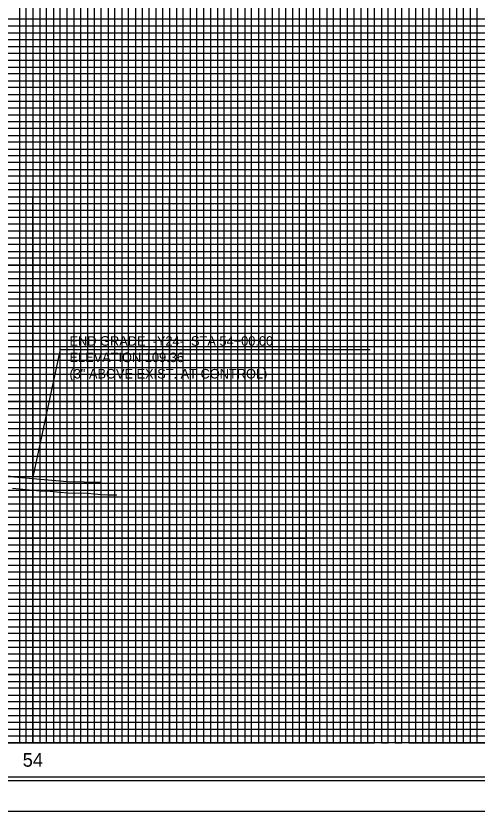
# Model space of a CAD drawing. Extents: x 2345490 to 2436403, y 465165 to 573888.
# Drawn here: x 2386154 to 2386492, y 515088 to 515670 of the extents above; entities that cross this region are included whole.
import ezdxf

# ---------------------------------------------------------------- set-up
doc = ezdxf.new("R2010")
doc.units = 0
for name, color, linetype in [('Old_Level_1', 7, 'Continuous'), ('Old_Level_18', 7, 'Continuous'), ('Old_Level_2', 7, 'Continuous'), ('Old_Level_41', 7, 'Continuous'), ('Old_Level_42', 7, 'Continuous'), ('Old_Level_43', 7, 'Continuous'), ('Old_Level_50', 7, 'Continuous'), ('Old_Level_51', 7, 'Continuous'), ('Old_Level_57', 7, 'Continuous'), ('Old_Level_61', 7, 'Continuous'), ('Old_Level_62', 7, 'Continuous'), ('Old_Level_63', 7, 'Continuous')]:
    doc.layers.add(name, color=color, linetype=linetype)

msp = doc.modelspace()

# ---------------------------------------------------------------- linework, layer by layer
at = {"layer": 'Old_Level_1'}
msp.add_lwpolyline([(2386151.799, 515323.96225), (2386156.799, 515323.5325), (2386161.799, 515323.10275), (2386166.799, 515322.673), (2386171.799, 515322.243), (2386176.799, 515322.05025), (2386181.799, 515321.5945), (2386186.799, 515321.139), (2386191.799, 515320.6835), (2386196.799, 515320.522), (2386201.799, 515320.5785), (2386206.799, 515320.42725), (2386211.799, 515319.972), (2386216.799, 515319.5165), (2386221.799, 515319.18175), (2386226.799, 515319.24875), (2386228.049, 515319.2575)], dxfattribs=at)
at = {"layer": 'Old_Level_18'}
msp.add_lwpolyline([(2387416.79875, 516162.5265), (2385916.79875, 516162.5265), (2385916.79875, 515112.5265), (2387416.79875, 515112.5265)], close=True, dxfattribs=at)
at = {"layer": 'Old_Level_2'}
for p, q in [((2386166.799, 515331.1265), (2386187.00475, 515425.63)), ((2386187.00475, 515425.63), (2386413.6105, 515425.63)), ((2386001.799, 515347.9565), (2386166.799, 515331.1265))]:
    msp.add_line(p, q, dxfattribs=at)
at = {"layer": 'Old_Level_41'}
msp.add_line((2387416.79875, 515137.5265), (2385916.79875, 515137.5265), dxfattribs=at)
for points in [[(2385916.79875, 516162.5265), (2385966.79875, 516162.5265), (2385966.79875, 515137.5265), (2386016.79875, 515137.5265), (2386016.79875, 516162.5265), (2386066.79875, 516162.5265), (2386066.79875, 515137.5265), (2386116.79875, 515137.5265), (2386116.79875, 516162.5265), (2386166.79875, 516162.5265), (2386166.79875, 515137.5265), (2386216.79875, 515137.5265), (2386216.79875, 516162.5265), (2386266.79875, 516162.5265), (2386266.79875, 515137.5265), (2386316.79875, 515137.5265), (2386316.79875, 516162.5265), (2386366.79875, 516162.5265), (2386366.79875, 515137.5265), (2386416.79875, 515137.5265), (2386416.79875, 516162.5265), (2386466.79875, 516162.5265), (2386466.79875, 515137.5265), (2386516.79875, 515137.5265)], [(2385991.79875, 515137.5265), (2385991.79875, 516162.5265), (2386041.79875, 516162.5265), (2386041.79875, 515137.5265), (2386091.79875, 515137.5265), (2386091.79875, 516162.5265), (2386141.79875, 516162.5265), (2386141.79875, 515137.5265), (2386191.79875, 515137.5265), (2386191.79875, 516162.5265), (2386241.79875, 516162.5265), (2386241.79875, 515137.5265), (2386291.79875, 515137.5265), (2386291.79875, 516162.5265), (2386341.79875, 516162.5265), (2386341.79875, 515137.5265), (2386391.79875, 515137.5265), (2386391.79875, 516162.5265), (2386441.79875, 516162.5265), (2386441.79875, 515137.5265), (2386491.79875, 515137.5265), (2386491.79875, 516162.5265), (2386541.79875, 516162.5265)], [(2387416.79875, 515662.5265), (2385916.79875, 515662.5265), (2385916.79875, 515612.5265), (2387416.79875, 515612.5265)], [(2387416.79875, 515562.5265), (2385916.79875, 515562.5265), (2385916.79875, 515512.5265), (2387416.79875, 515512.5265)], [(2387416.79875, 515487.5265), (2385916.79875, 515487.5265), (2385916.79875, 515537.5265), (2387416.79875, 515537.5265)], [(2387416.79875, 515462.5265), (2385916.79875, 515462.5265), (2385916.79875, 515412.5265), (2387416.79875, 515412.5265)], [(2387416.79875, 515387.5265), (2385916.79875, 515387.5265), (2385916.79875, 515437.5265), (2387416.79875, 515437.5265)], [(2387416.79875, 515362.5265), (2385916.79875, 515362.5265), (2385916.79875, 515312.5265), (2387416.79875, 515312.5265)], [(2387416.79875, 515262.5265), (2385916.79875, 515262.5265), (2385916.79875, 515212.5265), (2387416.79875, 515212.5265)], [(2387416.79875, 515187.5265), (2385916.79875, 515187.5265), (2385916.79875, 515237.5265), (2387416.79875, 515237.5265)], [(2387416.79875, 515162.5265), (2385916.79875, 515162.5265)]]:
    msp.add_lwpolyline(points, dxfattribs=at)
at = {"layer": 'Old_Level_42'}
for points in [[(2387416.79875, 515587.5265), (2385916.79875, 515587.5265), (2385916.79875, 515637.5265), (2387416.79875, 515637.5265)], [(2387416.79875, 515287.5265), (2385916.79875, 515287.5265), (2385916.79875, 515337.5265), (2387416.79875, 515337.5265)]]:
    msp.add_lwpolyline(points, dxfattribs=at)
at = {"layer": 'Old_Level_43'}
for points in [[(2386156.79875, 516162.5265), (2386156.79875, 515137.5265), (2386161.79875, 515137.5265), (2386161.79875, 516162.5265)], [(2386171.79875, 516162.5265), (2386171.79875, 515137.5265), (2386176.79875, 515137.5265), (2386176.79875, 516162.5265)], [(2386181.79875, 516162.5265), (2386181.79875, 515137.5265), (2386186.79875, 515137.5265), (2386186.79875, 516162.5265)], [(2386196.79875, 516162.5265), (2386196.79875, 515137.5265), (2386201.79875, 515137.5265), (2386201.79875, 516162.5265)], [(2386206.79875, 516162.5265), (2386206.79875, 515137.5265), (2386211.79875, 515137.5265), (2386211.79875, 516162.5265)], [(2386221.79875, 516162.5265), (2386221.79875, 515137.5265), (2386226.79875, 515137.5265), (2386226.79875, 516162.5265)], [(2386231.79875, 516162.5265), (2386231.79875, 515137.5265), (2386236.79875, 515137.5265), (2386236.79875, 516162.5265)], [(2386246.79875, 516162.5265), (2386246.79875, 515137.5265), (2386251.79875, 515137.5265), (2386251.79875, 516162.5265)], [(2386256.79875, 516162.5265), (2386256.79875, 515137.5265), (2386261.79875, 515137.5265), (2386261.79875, 516162.5265)], [(2386271.79875, 516162.5265), (2386271.79875, 515137.5265), (2386276.79875, 515137.5265), (2386276.79875, 516162.5265)], [(2386281.79875, 516162.5265), (2386281.79875, 515137.5265), (2386286.79875, 515137.5265), (2386286.79875, 516162.5265)], [(2386296.79875, 516162.5265), (2386296.79875, 515137.5265), (2386311.79875, 515137.5265), (2386311.79875, 516162.5265)], [(2386301.79875, 516162.5265), (2386301.79875, 515137.5265), (2386306.79875, 515137.5265), (2386306.79875, 516162.5265)], [(2386301.79875, 516161.9265), (2386301.79875, 515137.5265), (2386306.79875, 515137.5265), (2386306.79875, 516161.9265)], [(2386321.79875, 516162.5265), (2386321.79875, 515137.5265), (2386326.79875, 515137.5265), (2386326.79875, 516162.5265)], [(2386331.79875, 516162.5265), (2386331.79875, 515137.5265), (2386336.79875, 515137.5265), (2386336.79875, 516162.5265)], [(2386346.79875, 516162.5265), (2386346.79875, 515137.5265), (2386351.79875, 515137.5265), (2386351.79875, 516162.5265)], [(2386356.79875, 516162.5265), (2386356.79875, 515137.5265), (2386361.79875, 515137.5265), (2386361.79875, 516162.5265)], [(2386371.79875, 516162.5265), (2386371.79875, 515137.5265), (2386376.79875, 515137.5265), (2386376.79875, 516162.5265)], [(2386381.79875, 516162.5265), (2386381.79875, 515137.5265), (2386386.79875, 515137.5265), (2386386.79875, 516162.5265)], [(2386396.79875, 516162.5265), (2386396.79875, 515137.5265), (2386401.79875, 515137.5265), (2386401.79875, 516162.5265)], [(2386406.79875, 516162.5265), (2386406.79875, 515137.5265), (2386411.79875, 515137.5265), (2386411.79875, 516162.5265)], [(2386421.79875, 516162.5265), (2386421.79875, 515137.5265), (2386426.79875, 515137.5265), (2386426.79875, 516162.5265)], [(2386431.79875, 516162.5265), (2386431.79875, 515137.5265), (2386436.79875, 515137.5265), (2386436.79875, 516162.5265)], [(2386446.79875, 516162.5265), (2386446.79875, 515137.5265)], [(2386451.79875, 516162.5265), (2386451.79875, 515137.5265), (2386456.79875, 515137.5265), (2386456.79875, 516162.5265), (2386461.79875, 516162.5265), (2386461.79875, 515137.5265), (2386471.79875, 515137.5265), (2386471.79875, 516162.5265), (2386476.79875, 516162.5265), (2386476.79875, 515137.5265), (2386481.79875, 515137.5265), (2386481.79875, 516162.5265), (2386486.79875, 516162.5265), (2386486.79875, 515137.5265)], [(2387366.79875, 515667.5265), (2385966.79875, 515667.5265), (2385966.79875, 515657.5265), (2387366.79875, 515657.5265)], [(2387366.79875, 515652.5265), (2385966.79875, 515652.5265), (2385966.79875, 515647.5265), (2387366.79875, 515647.5265)], [(2387366.79875, 515642.5265), (2385966.79875, 515642.5265)], [(2385966.79875, 515632.5265), (2387366.79875, 515632.5265)], [(2387366.79875, 515627.5265), (2385966.79875, 515627.5265), (2385966.79875, 515622.5265), (2387366.79875, 515622.5265)], [(2387366.79875, 515617.5265), (2385966.79875, 515617.5265), (2385966.79875, 515607.5265), (2387366.79875, 515607.5265)], [(2387366.79875, 515602.5265), (2385966.79875, 515602.5265), (2385966.79875, 515597.5265), (2387366.79875, 515597.5265)], [(2387366.79875, 515592.5265), (2385966.79875, 515592.5265), (2385966.79875, 515582.5265), (2387366.79875, 515582.5265)], [(2387366.79875, 515577.5265), (2385966.79875, 515577.5265), (2385966.79875, 515572.5265), (2387366.79875, 515572.5265)], [(2387366.79875, 515567.5265), (2385966.79875, 515567.5265), (2385966.79875, 515557.5265), (2387366.79875, 515557.5265)], [(2387366.79875, 515552.5265), (2385966.79875, 515552.5265), (2385966.79875, 515547.5265), (2387366.79875, 515547.5265)], [(2387366.79875, 515542.5265), (2385966.79875, 515542.5265), (2385966.79875, 515532.5265), (2387366.79875, 515532.5265)], [(2387366.79875, 515527.5265), (2385966.79875, 515527.5265), (2385966.79875, 515522.5265), (2387366.79875, 515522.5265)], [(2387366.79875, 515517.5265), (2385966.79875, 515517.5265), (2385966.79875, 515507.5265), (2387366.79875, 515507.5265)], [(2387366.79875, 515502.5265), (2385966.79875, 515502.5265), (2385966.79875, 515497.5265), (2387366.79875, 515497.5265)], [(2387366.79875, 515492.5265), (2385966.79875, 515492.5265), (2385966.79875, 515482.5265), (2387366.79875, 515482.5265)], [(2387366.79875, 515477.5265), (2385966.79875, 515477.5265), (2385966.79875, 515472.5265), (2387366.79875, 515472.5265)], [(2387366.79875, 515467.5265), (2385966.79875, 515467.5265), (2385966.79875, 515457.5265), (2387366.79875, 515457.5265)], [(2387366.79875, 515452.5265), (2385966.79875, 515452.5265), (2385966.79875, 515447.5265), (2387366.79875, 515447.5265)], [(2387366.79875, 515442.5265), (2385966.79875, 515442.5265), (2385966.79875, 515432.5265), (2387366.79875, 515432.5265)], [(2387366.79875, 515427.5265), (2385966.79875, 515427.5265), (2385966.79875, 515422.5265), (2387366.79875, 515422.5265)], [(2387366.79875, 515417.5265), (2385966.79875, 515417.5265), (2385966.79875, 515407.5265), (2387366.79875, 515407.5265)], [(2387366.79875, 515402.5265), (2385966.79875, 515402.5265), (2385966.79875, 515397.5265), (2387366.79875, 515397.5265)], [(2387366.79875, 515392.5265), (2385966.79875, 515392.5265), (2385966.79875, 515382.5265), (2387366.79875, 515382.5265)], [(2387366.79875, 515377.5265), (2385966.79875, 515377.5265), (2385966.79875, 515372.5265), (2387366.79875, 515372.5265)], [(2387366.79875, 515367.5265), (2385966.79875, 515367.5265), (2385966.79875, 515357.5265), (2387366.79875, 515357.5265)], [(2387366.79875, 515352.5265), (2385966.79875, 515352.5265), (2385966.79875, 515347.5265), (2387366.79875, 515347.5265)], [(2387366.79875, 515342.5265), (2385966.79875, 515342.5265)], [(2385966.79875, 515332.5265), (2387366.79875, 515332.5265)], [(2387366.79875, 515327.5265), (2385966.79875, 515327.5265), (2385966.79875, 515322.5265), (2387366.79875, 515322.5265)], [(2387366.79875, 515317.5265), (2385966.79875, 515317.5265)], [(2385966.79875, 515307.5265), (2387366.79875, 515307.5265)], [(2387366.79875, 515302.5265), (2385966.79875, 515302.5265), (2385966.79875, 515297.5265), (2387366.79875, 515297.5265)], [(2387366.79875, 515292.5265), (2385966.79875, 515292.5265), (2385966.79875, 515282.5265), (2387366.79875, 515282.5265)], [(2387366.79875, 515277.5265), (2385966.79875, 515277.5265), (2385966.79875, 515272.5265), (2387366.79875, 515272.5265)], [(2387366.79875, 515267.5265), (2385966.79875, 515267.5265), (2385966.79875, 515257.5265), (2387366.79875, 515257.5265)], [(2387366.79875, 515252.5265), (2385966.79875, 515252.5265), (2385966.79875, 515247.5265), (2387366.79875, 515247.5265)], [(2387366.79875, 515242.5265), (2385966.79875, 515242.5265), (2385966.79875, 515232.5265), (2387366.79875, 515232.5265)], [(2387366.79875, 515227.5265), (2385966.79875, 515227.5265), (2385966.79875, 515222.5265), (2387366.79875, 515222.5265)], [(2387366.79875, 515217.5265), (2385966.79875, 515217.5265), (2385966.79875, 515207.5265), (2387366.79875, 515207.5265)], [(2387366.79875, 515202.5265), (2385966.79875, 515202.5265), (2385966.79875, 515197.5265), (2387366.79875, 515197.5265)], [(2387366.79875, 515192.5265), (2385966.79875, 515192.5265), (2385966.79875, 515182.5265), (2387366.79875, 515182.5265)], [(2387366.79875, 515177.5265), (2385966.79875, 515177.5265), (2385966.79875, 515172.5265), (2387366.79875, 515172.5265)], [(2387366.79875, 515167.5265), (2385966.79875, 515167.5265), (2385966.79875, 515157.5265), (2387366.79875, 515157.5265)], [(2387366.79875, 515152.5265), (2385966.79875, 515152.5265), (2385966.79875, 515147.5265), (2387366.79875, 515147.5265)], [(2387366.79875, 515142.5265), (2385966.79875, 515142.5265)]]:
    msp.add_lwpolyline(points, dxfattribs=at)
at = {"layer": 'Old_Level_50'}
msp.add_lwpolyline([(2387429.29875, 516165.0765), (2385762.79875, 516165.0765), (2385762.79875, 515109.9765), (2387429.29875, 515109.9765)], close=True, dxfattribs=at)
at = {"layer": 'Old_Level_51'}
msp.add_lwpolyline([(2387433.79875, 516187.5265), (2385749.79875, 516187.5265), (2385749.79875, 515087.5265), (2387433.79875, 515087.5265)], close=True, dxfattribs=at)
at = {"layer": 'Old_Level_57'}
for p, q in [((2381716.79925, 515537.52675), (2386366.79875, 515537.52675)), ((2386166.79875, 515137.52675), (2386166.79875, 515537.52675)), ((2386166.79875, 515137.62675), (2386166.79875, 515537.52675)), ((2386266.79875, 515137.52675), (2386266.79875, 515537.52675)), ((2386266.79875, 515137.62675), (2386266.79875, 515537.52675)), ((2386366.79875, 515137.52675), (2386366.79875, 515537.52675)), ((2386366.79875, 515137.62675), (2386366.79875, 515537.52675)), ((2381716.79925, 515487.52675), (2386366.79875, 515487.52675)), ((2381716.79925, 515437.52675), (2386366.79875, 515437.52675)), ((2381716.79925, 515387.52675), (2386366.79875, 515387.52675)), ((2381716.79925, 515337.52675), (2386366.79875, 515337.52675)), ((2381716.79925, 515287.52675), (2386366.79875, 515287.52675)), ((2381716.79925, 515237.52675), (2386366.79875, 515237.52675)), ((2381716.799, 515187.52675), (2386366.79875, 515187.52675)), ((2381716.79925, 515137.52675), (2386366.79875, 515137.52675))]:
    msp.add_line(p, q, dxfattribs=at)
at = {"layer": 'Old_Level_61'}
msp.add_lwpolyline([(2385816.799, 515360.83725), (2385841.799, 515359.5115), (2385866.799, 515357.81875), (2385891.799, 515356.088), (2385916.799, 515354.1045), (2385941.799, 515351.92675), (2385966.799, 515349.79575), (2385991.799, 515347.73775), (2386016.799, 515345.5835), (2386041.799, 515343.3765), (2386066.799, 515341.1295), (2386091.799, 515337.8655), (2386116.799, 515335.614), (2386141.799, 515333.36375), (2386166.799, 515331.09625), (2386191.799, 515328.91725), (2386216.799, 515328.358)], dxfattribs=at)
at = {"layer": 'Old_Level_63'}
msp.add_line((2381766.79875, 515137.5265), (2386228.05125, 515137.5265), dxfattribs=at)

# ---------------------------------------------------------------- texts
at = {"layer": 'Old_Level_2'}
for s, p in [('END GRADE  -Y24-  STA 54+00.00', (2386193.49425, 515428.4135)), ('ELEVATION 109.36 ', (2386193.49425, 515416.4135)), ('(3" ABOVE EXIST. AT CONTROL)', (2386193.49425, 515404.4135))]:
    msp.add_text(s, height=7.0000005, dxfattribs=at).set_placement(p)
at = {"layer": 'Old_Level_62'}
msp.add_text('54', height=10.000001, dxfattribs=at).set_placement((2386159.2505, 515120.0265))

doc.saveas('drawing.dxf')
